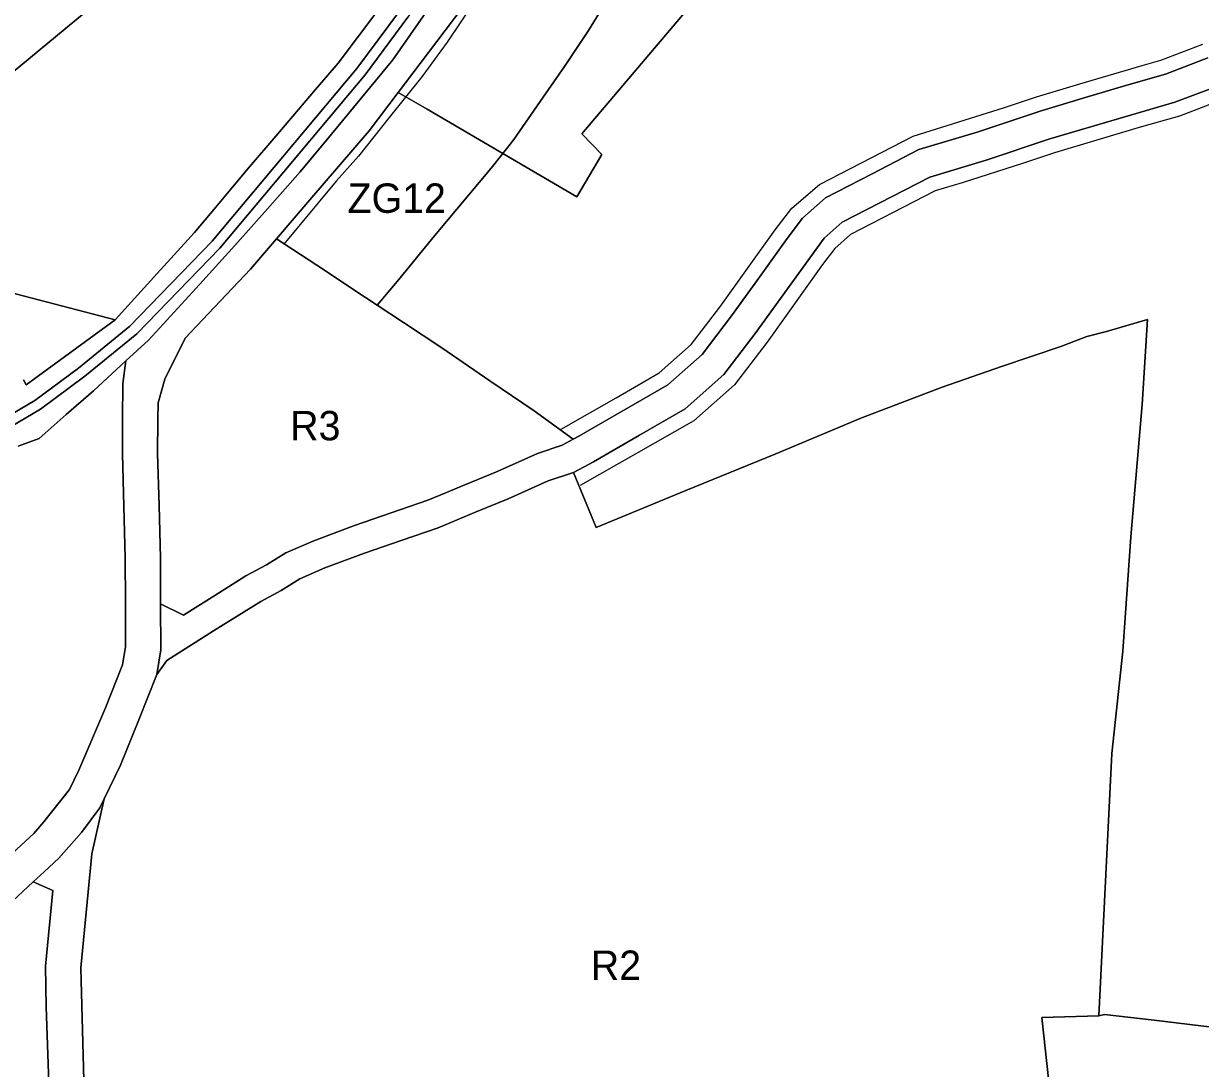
# Model space of a CAD drawing. Extents: x 7428841 to 7433518, y 5545054 to 5546840.
# Drawn here: x 7429514.3 to 7429914.7, y 5545549.4 to 5545904.8 of the extents above; entities that cross this region are included whole.
import ezdxf

# ---------------------------------------------------------------- set-up
doc = ezdxf.new("R2010")
doc.units = 0
for name, color, linetype in [('linie_rozgraniczajace', 7, 'Continuous'), ('linie_zabudowy_nieprzekraczalne', 7, 'Continuous'), ('oznaczenia_przeznaczen', 7, 'Continuous')]:
    doc.layers.add(name, color=color, linetype=linetype)

msp = doc.modelspace()

# ---------------------------------------------------------------- linework, layer by layer
at = {"layer": 'linie_rozgraniczajace'}
for points in [[(7429932.61, 5546245.81), (7429916.65, 5546236.37), (7429890.04, 5546217.47), (7429868.53, 5546200.53), (7429844.24, 5546182.48), (7429819.06, 5546159.11), (7429803.55, 5546141.79), (7429775.47, 5546107.09), (7429727.84, 5546041.79), (7429712.38, 5546019.62), (7429694.69, 5545991.97), (7429678.9, 5545965.27), (7429661.41, 5545937.52), (7429642.2, 5545909.04), (7429627.76, 5545889.55), (7429578.46, 5545830.77), (7429550.53, 5545801.9), (7429533.05, 5545787.63), (7429518.17, 5545776.56), (7429482.58, 5545755.61)], [(7429482.58, 5545755.61), (7429518.17, 5545776.56), (7429533.05, 5545787.63), (7429550.53, 5545801.9), (7429578.46, 5545830.77), (7429627.76, 5545889.55), (7429642.2, 5545909.04), (7429661.41, 5545937.52), (7429678.9, 5545965.27), (7429694.69, 5545991.97), (7429712.38, 5546019.62), (7429727.84, 5546041.79), (7429775.47, 5546107.09), (7429803.55, 5546141.79), (7429819.06, 5546159.11), (7429844.24, 5546182.48), (7429868.53, 5546200.53), (7429890.04, 5546217.47), (7429916.65, 5546236.37), (7429932.61, 5546245.81)], [(7429914.81, 5546230.77), (7429892.14, 5546214.67), (7429870.66, 5546197.75), (7429846.48, 5546179.78), (7429821.56, 5546156.65), (7429806.22, 5546139.52), (7429778.24, 5546104.95), (7429730.69, 5546039.75), (7429715.29, 5546017.67), (7429704.85, 5546001.35), (7429698.85, 5545991.98), (7429697.67, 5545990.14), (7429681.88, 5545963.44), (7429664.34, 5545935.61), (7429645.05, 5545907.02), (7429630.51, 5545887.39), (7429581.07, 5545828.42), (7429552.9, 5545799.32), (7429535.21, 5545784.87), (7429520.11, 5545773.64), (7429483.94, 5545752.35)], [(7429514.31, 5545783.59), (7429515.27, 5545781.89), (7429545.46, 5545804.09), (7429559.76, 5545819.83), (7429572.5, 5545833.72), (7429579.76, 5545842.36), (7429585.45, 5545849.15), (7429591.17, 5545856.04), (7429600.14, 5545866.56), (7429613.69, 5545882.38), (7429621.41, 5545891.37), (7429641.03, 5545917.61), (7429649.35, 5545928.71), (7429660.9, 5545946.85), (7429669.22, 5545959.93), (7429675.56, 5545970.15), (7429679.11, 5545976.01), (7429688.22, 5545991.91), (7429693.81, 5546002.15), (7429701.98, 5546014.44), (7429709, 5546025.01), (7429715.29, 5546034.7)], [(7429746.06, 5545916.73), (7429704.27, 5545867.25), (7429711.02, 5545860.3), (7429702.59, 5545845.87), (7429677.35, 5545860.63), (7429681.06, 5545865.42), (7429691.06, 5545879.77), (7429698.36, 5545890.17), (7429706.56, 5545902.43), (7429722.17, 5545928)], [(7429641.03, 5545917.61), (7429621.41, 5545891.37), (7429613.69, 5545882.38), (7429600.14, 5545866.56), (7429591.17, 5545856.04), (7429585.45, 5545849.15), (7429579.76, 5545842.36), (7429572.5, 5545833.72), (7429559.76, 5545819.83), (7429545.46, 5545804.09), (7429503.66, 5545814.98)], [(7429509.13, 5545621.31), (7429517.79, 5545629.38), (7429521.27, 5545633.31), (7429529.96, 5545644.33), (7429533.14, 5545650.89), (7429542.19, 5545672.07), (7429548.05, 5545686.68), (7429549.02, 5545692.79), (7429548.98, 5545707.88), (7429548.95, 5545722.97), (7429548.46, 5545740.72), (7429547.96, 5545758.47), (7429548.05, 5545770.42), (7429548.13, 5545782.37), (7429549.13, 5545790.07), (7429556.9, 5545797.17), (7429571.81, 5545813.43), (7429575.3, 5545817.27), (7429586.23, 5545829.31), (7429597.31, 5545841.81), (7429608.4, 5545854.32), (7429619.06, 5545867.19), (7429639.95, 5545892.51), (7429657.22, 5545917.24)], [(7429657.22, 5545917.24), (7429639.95, 5545892.51), (7429619.06, 5545867.19), (7429608.4, 5545854.32), (7429597.31, 5545841.81), (7429586.23, 5545829.31), (7429575.3, 5545817.27), (7429571.81, 5545813.43), (7429556.9, 5545797.17), (7429549.13, 5545790.07), (7429538.16, 5545779.92), (7429528.88, 5545771.81), (7429519.61, 5545763.69), (7429512.51, 5545761.03)], [(7429494.94, 5545875.35), (7429540.93, 5545913.47)], [(7429540.93, 5545913.47), (7429494.94, 5545875.35)], [(7429666.61, 5545914.27), (7429649.27, 5545891.27), (7429641.81, 5545881.38), (7429631.93, 5545868.28), (7429611.76, 5545844.8), (7429600.39, 5545831.57), (7429591.58, 5545821.32), (7429577.26, 5545806.14), (7429569.36, 5545797.78), (7429562.38, 5545783.91), (7429560.08, 5545775.81), (7429560.04, 5545770.07), (7429559.96, 5545758.6), (7429560.46, 5545740.87), (7429560.95, 5545723.15), (7429560.98, 5545707.5), (7429561.02, 5545691.86), (7429559.69, 5545683.47), (7429553.5, 5545668.04), (7429547.3, 5545652.6), (7429541.74, 5545641.12), (7429540.27, 5545638.1), (7429534.08, 5545629.69), (7429526.4, 5545621), (7429521.33, 5545616.28), (7429517.67, 5545612.86), (7429508.94, 5545604.73)], [(7429917.2, 5545893.14), (7429902.74, 5545887.57), (7429889.65, 5545883.83), (7429875.05, 5545879.5), (7429860.44, 5545875.16), (7429838.7, 5545867.87), (7429818.81, 5545861.92), (7429802.99, 5545853.72), (7429787.16, 5545845.53), (7429779.29, 5545838.62), (7429774.07, 5545831.72), (7429764.62, 5545818.54), (7429755.18, 5545805.37), (7429745.14, 5545792.25), (7429733.51, 5545781.92), (7429703.25, 5545764.44), (7429701.31, 5545763.41), (7429688.04, 5545773.11), (7429672.91, 5545783.34), (7429656.59, 5545794.52), (7429643.61, 5545803.08), (7429634.57, 5545809.05), (7429641.47, 5545817.06), (7429654.16, 5545832.59), (7429673.38, 5545855.63), (7429677.35, 5545860.63), (7429702.59, 5545845.87), (7429711.02, 5545860.3), (7429704.27, 5545867.25), (7429746.06, 5545916.73)], [(7429483.94, 5545752.35), (7429520.11, 5545773.64), (7429535.21, 5545784.87), (7429552.9, 5545799.32), (7429581.07, 5545828.42), (7429630.51, 5545887.39), (7429645.05, 5545907.02)], [(7429559.69, 5545683.47), (7429561.02, 5545691.86), (7429560.98, 5545707.5), (7429568.79, 5545703.62), (7429579.4, 5545710.29), (7429590, 5545716.97), (7429597.02, 5545720.66), (7429603.6, 5545724.77), (7429608.32, 5545726.84), (7429613.04, 5545728.92), (7429619.98, 5545731.52), (7429626.91, 5545734.12), (7429651.84, 5545742.66), (7429658.15, 5545745.3), (7429664.46, 5545747.94), (7429675.27, 5545752.34), (7429689.16, 5545758.57), (7429697.55, 5545761.4), (7429701.31, 5545763.41), (7429703.25, 5545764.44), (7429733.51, 5545781.92), (7429745.14, 5545792.25), (7429755.18, 5545805.37), (7429764.62, 5545818.54), (7429774.07, 5545831.72), (7429779.29, 5545838.62), (7429787.16, 5545845.53), (7429802.99, 5545853.72), (7429818.81, 5545861.92), (7429838.7, 5545867.87), (7429860.44, 5545875.16), (7429875.05, 5545879.5), (7429889.65, 5545883.83), (7429902.74, 5545887.57), (7429917.2, 5545893.14)], [(7429925.35, 5545885.29), (7429905.91, 5545878.08), (7429863.46, 5545865.63), (7429841.72, 5545858.33), (7429822.57, 5545852.61), (7429792.84, 5545837.21), (7429786.65, 5545831.78), (7429763.22, 5545799.41), (7429752.5, 5545785.41), (7429739.39, 5545773.77), (7429723.82, 5545764.78), (7429708.25, 5545755.78), (7429701.58, 5545752.21), (7429701.45, 5545752.17), (7429692.81, 5545749.25), (7429686.01, 5545746.2), (7429679.21, 5545743.14), (7429668.27, 5545738.7), (7429655.39, 5545733.31), (7429642.84, 5545729.01), (7429630.29, 5545724.71), (7429616.81, 5545719.65), (7429608.28, 5545715.91), (7429602, 5545711.98), (7429595, 5545708.3), (7429579.01, 5545698.24), (7429563.03, 5545688.18), (7429559.69, 5545683.47)], [(7429925.98, 5545562.57), (7429898.92, 5545565.83), (7429882.03, 5545567.76), (7429880.1, 5545567.32), (7429884.46, 5545656.54), (7429888.26, 5545691.35), (7429891.02, 5545730.26), (7429894.85, 5545775.23), (7429896.6, 5545804.1), (7429882.75, 5545800.12), (7429876.02, 5545798.38), (7429867.2, 5545795.01), (7429847.02, 5545788.13), (7429826.84, 5545781.17), (7429799.18, 5545770.63), (7429770.25, 5545758.44), (7429739.65, 5545745.94), (7429709.06, 5545733.43), (7429701.45, 5545752.17), (7429701.58, 5545752.21), (7429708.25, 5545755.78), (7429723.82, 5545764.78), (7429739.39, 5545773.77), (7429752.5, 5545785.41), (7429763.22, 5545799.41), (7429786.65, 5545831.78), (7429792.84, 5545837.21), (7429822.57, 5545852.61), (7429841.72, 5545858.33), (7429863.46, 5545865.63), (7429905.91, 5545878.08), (7429925.35, 5545885.29)], [(7429503.66, 5545814.98), (7429545.46, 5545804.09), (7429515.27, 5545781.89), (7429514.31, 5545783.59)], [(7429534.88, 5545545.43), (7429533.78, 5545583.68), (7429537.58, 5545622.38), (7429541.74, 5545641.12), (7429547.3, 5545652.6), (7429553.5, 5545668.04), (7429559.69, 5545683.47), (7429563.03, 5545688.18), (7429579.01, 5545698.24), (7429595, 5545708.3), (7429602, 5545711.98), (7429608.28, 5545715.91), (7429616.81, 5545719.65), (7429630.29, 5545724.71), (7429642.84, 5545729.01), (7429655.39, 5545733.31), (7429668.27, 5545738.7), (7429679.21, 5545743.14), (7429686.01, 5545746.2), (7429692.81, 5545749.25), (7429701.45, 5545752.17), (7429709.06, 5545733.43), (7429739.65, 5545745.94), (7429770.25, 5545758.44), (7429799.18, 5545770.63), (7429826.84, 5545781.17), (7429847.02, 5545788.13), (7429867.2, 5545795.01), (7429876.02, 5545798.38), (7429882.75, 5545800.12), (7429896.6, 5545804.1), (7429894.85, 5545775.23), (7429891.02, 5545730.26), (7429888.26, 5545691.35), (7429884.46, 5545656.54), (7429880.1, 5545567.32), (7429860.76, 5545566.76), (7429863.08, 5545544.91)], [(7429512.51, 5545761.03), (7429519.61, 5545763.69), (7429528.88, 5545771.81), (7429538.16, 5545779.92), (7429549.13, 5545790.07), (7429548.13, 5545782.37), (7429548.05, 5545770.42), (7429547.96, 5545758.47), (7429548.46, 5545740.72), (7429548.95, 5545722.97), (7429548.98, 5545707.88), (7429549.02, 5545692.79), (7429548.05, 5545686.68), (7429542.19, 5545672.07), (7429533.14, 5545650.89), (7429529.96, 5545644.33), (7429521.27, 5545633.31), (7429517.79, 5545629.38), (7429509.13, 5545621.31)], [(7429522.9, 5545544.57), (7429521.99, 5545570.36), (7429521.77, 5545584.17), (7429524.31, 5545610.01), (7429517.67, 5545612.86), (7429521.33, 5545616.28), (7429526.4, 5545621), (7429534.08, 5545629.69), (7429540.27, 5545638.1), (7429541.74, 5545641.12), (7429537.58, 5545622.38), (7429533.78, 5545583.68), (7429534.88, 5545545.43)], [(7429508.94, 5545604.73), (7429517.67, 5545612.86), (7429524.31, 5545610.01), (7429521.77, 5545584.17), (7429521.99, 5545570.36), (7429522.9, 5545544.57), (7429523.81, 5545518.79), (7429529.09, 5545492.31), (7429534.36, 5545465.82), (7429539.51, 5545438.69), (7429545.49, 5545428.17), (7429551.07, 5545419.83), (7429538.24, 5545420.68), (7429538.25, 5545418.47), (7429533.26, 5545355.15), (7429532.6, 5545322.55), (7429522.06, 5545316.24), (7429511.53, 5545309.92)], [(7429863.08, 5545544.91), (7429860.76, 5545566.76), (7429880.1, 5545567.32), (7429882.03, 5545567.76), (7429898.92, 5545565.83), (7429925.98, 5545562.57)]]:
    msp.add_lwpolyline(points, dxfattribs=at)
for points in [[(7429641.81, 5545881.38), (7429649.27, 5545891.27), (7429666.61, 5545914.27), (7429682.05, 5545940.18), (7429697.48, 5545966.08), (7429706.14, 5545976.78), (7429712, 5545981.08), (7429727.19, 5545985.3), (7429742.37, 5545989.53), (7429764.65, 5545993.84), (7429757.26, 5545982.98), (7429758.12, 5545974.05), (7429751.29, 5545973.39), (7429737.44, 5545952.4), (7429728.4, 5545938.93), (7429723.32, 5545930.25), (7429722.17, 5545928), (7429706.56, 5545902.43), (7429698.36, 5545890.17), (7429691.06, 5545879.77), (7429681.06, 5545865.42), (7429677.35, 5545860.63), (7429651.64, 5545875.64)], [(7429600.39, 5545831.57), (7429611.76, 5545844.8), (7429631.93, 5545868.28), (7429641.81, 5545881.38), (7429651.64, 5545875.64), (7429677.35, 5545860.63), (7429673.38, 5545855.63), (7429654.16, 5545832.59), (7429641.47, 5545817.06), (7429634.57, 5545809.05), (7429630.64, 5545811.64), (7429614.08, 5545822.63)], [(7429560.98, 5545707.5), (7429560.95, 5545723.15), (7429560.46, 5545740.87), (7429559.96, 5545758.6), (7429560.04, 5545770.07), (7429560.08, 5545775.81), (7429562.38, 5545783.91), (7429569.36, 5545797.78), (7429577.26, 5545806.14), (7429591.58, 5545821.32), (7429600.39, 5545831.57), (7429614.08, 5545822.63), (7429630.64, 5545811.64), (7429634.57, 5545809.05), (7429643.61, 5545803.08), (7429656.59, 5545794.52), (7429672.91, 5545783.34), (7429688.04, 5545773.11), (7429701.31, 5545763.41), (7429697.55, 5545761.4), (7429689.16, 5545758.57), (7429675.27, 5545752.34), (7429664.46, 5545747.94), (7429658.15, 5545745.3), (7429651.84, 5545742.66), (7429626.91, 5545734.12), (7429619.98, 5545731.52), (7429613.04, 5545728.92), (7429608.32, 5545726.84), (7429603.6, 5545724.77), (7429597.02, 5545720.66), (7429590, 5545716.97), (7429579.4, 5545710.29), (7429568.79, 5545703.62)]]:
    msp.add_lwpolyline(points, close=True, dxfattribs=at)
at = {"layer": 'linie_zabudowy_nieprzekraczalne'}
for points in [[(7429667.49, 5545911.95), (7429658.45, 5545898.47), (7429649.79, 5545886.66), (7429638.69, 5545872.8), (7429628.31, 5545859.67), (7429620.7, 5545851.23), (7429602.87, 5545829.78)], [(7429697.22, 5545766.9), (7429715.89, 5545777.52), (7429730.57, 5545786), (7429741.46, 5545795.67), (7429751.16, 5545808.34), (7429770.04, 5545834.68), (7429775.63, 5545842.07), (7429785.09, 5545850.12), (7429816.9, 5545866.56), (7429848.03, 5545876.27), (7429858.93, 5545879.93), (7429873.63, 5545884.3), (7429894.81, 5545890.51), (7429901.15, 5545892.32), (7429915.52, 5545897.85)], [(7429922.24, 5545879.01), (7429907.5, 5545873.33), (7429893.85, 5545869.43), (7429864.96, 5545860.86), (7429854.14, 5545857.23), (7429833.62, 5545850.69), (7429824.46, 5545847.95), (7429795.68, 5545833.05), (7429790.33, 5545828.35), (7429786.15, 5545822.83), (7429767.24, 5545796.44), (7429756.18, 5545781.99), (7429742.32, 5545769.69), (7429703.72, 5545747.67)]]:
    msp.add_lwpolyline(points, dxfattribs=at)

# ---------------------------------------------------------------- texts
at = {"layer": 'oznaczenia_przeznaczen'}
for s, p in [('ZG12', (7429624.56, 5545840.43)), ('R3', (7429605.04, 5545763.06)), ('R2', (7429707.29, 5545579.54))]:
    msp.add_text(s, height=10, dxfattribs=at).set_placement(p)

doc.saveas('drawing.dxf')
